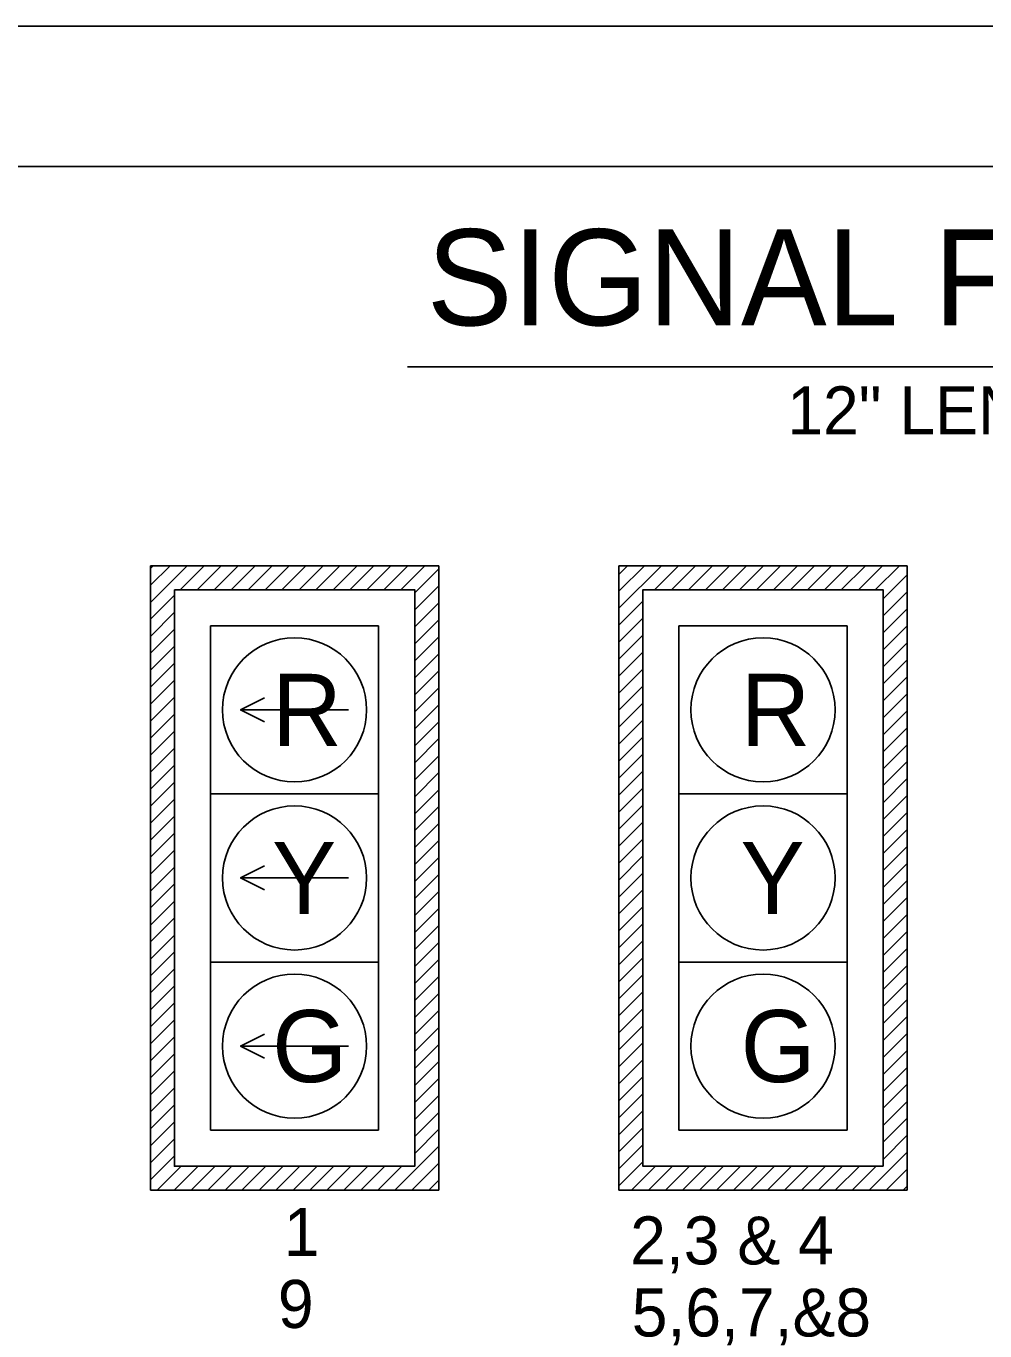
# Model space of a CAD drawing. Extents: x 660063 to 664816, y 641756 to 643817.
# Drawn here: x 661614.4 to 661694.2, y 642780 to 642888.7 of the extents above; entities that cross this region are included whole.
import ezdxf

# ---------------------------------------------------------------- set-up
doc = ezdxf.new("R2010")
doc.units = 0
for name, color, linetype in [('Default', 7, 'Continuous'), ('R_Border', 7, 'Continuous'), ('R_No Plot', 7, 'Continuous'), ('T_Drafting', 7, 'Continuous'), ('T_Notes', 7, 'Continuous')]:
    doc.layers.add(name, color=color, linetype=linetype)

msp = doc.modelspace()

# ---------------------------------------------------------------- linework, layer by layer
at = {"layer": 'R_Border'}
msp.add_line((661447.99, 642876.97), (662396.53, 642876.97), dxfattribs=at)
at = {"layer": 'R_No Plot'}
msp.add_line((661410.79, 642888.66), (662410.79, 642888.66), dxfattribs=at)
msp.add_lwpolyline([(661410.77, 642888.66), (662410.79, 642888.66), (662410.79, 642248.64), (661410.77, 642248.64)], close=True, dxfattribs=at)
at = {"layer": 'T_Drafting'}
for p, q in [((661624.76, 642843.72), (661648.76, 642843.72)), ((661624.76, 642791.72), (661624.76, 642843.72)), ((661624.76, 642840.67), (661627.81, 642843.72)), ((661624.76, 642842.09), (661626.4, 642843.72)), ((661624.76, 642843.5), (661624.99, 642843.72)), ((661627.23, 642841.72), (661629.23, 642843.72)), ((661628.64, 642841.72), (661630.64, 642843.72)), ((661630.06, 642841.72), (661632.06, 642843.72)), ((661631.47, 642841.72), (661633.47, 642843.72)), ((661632.89, 642841.72), (661634.89, 642843.72)), ((661634.3, 642841.72), (661636.3, 642843.72)), ((661635.71, 642841.72), (661637.71, 642843.72)), ((661637.13, 642841.72), (661639.13, 642843.72)), ((661638.54, 642841.72), (661640.54, 642843.72)), ((661639.96, 642841.72), (661641.96, 642843.72)), ((661641.37, 642841.72), (661643.37, 642843.72)), ((661642.78, 642841.72), (661644.78, 642843.72)), ((661644.2, 642841.72), (661646.2, 642843.72)), ((661645.61, 642841.72), (661647.61, 642843.72)), ((661646.76, 642841.46), (661648.76, 642843.46)), ((661648.76, 642843.72), (661648.76, 642791.72)), ((661687.76, 642843.72), (661663.76, 642843.72)), ((661663.76, 642843.72), (661663.76, 642791.72)), ((661663.76, 642840.18), (661667.31, 642843.72)), ((661663.76, 642841.59), (661665.9, 642843.72)), ((661663.76, 642843), (661664.48, 642843.72)), ((661666.73, 642841.72), (661668.73, 642843.72)), ((661668.14, 642841.72), (661670.14, 642843.72)), ((661669.55, 642841.72), (661671.55, 642843.72)), ((661670.97, 642841.72), (661672.97, 642843.72)), ((661672.38, 642841.72), (661674.38, 642843.72)), ((661673.8, 642841.72), (661675.8, 642843.72)), ((661675.21, 642841.72), (661677.21, 642843.72)), ((661676.62, 642841.72), (661678.62, 642843.72)), ((661678.04, 642841.72), (661680.04, 642843.72)), ((661679.45, 642841.72), (661681.45, 642843.72)), ((661680.87, 642841.72), (661682.87, 642843.72)), ((661682.28, 642841.72), (661684.28, 642843.72)), ((661683.7, 642841.72), (661685.7, 642843.72)), ((661685.11, 642841.72), (661687.11, 642843.72)), ((661687.76, 642791.72), (661687.76, 642843.72)), ((661685.76, 642840.96), (661687.76, 642842.96)), ((661624.76, 642839.26), (661626.76, 642841.26)), ((661646.76, 642840.04), (661648.76, 642842.04)), ((661685.76, 642839.55), (661687.76, 642841.55)), ((661646.76, 642838.63), (661648.76, 642840.63)), ((661663.76, 642838.76), (661665.76, 642840.76)), ((661685.76, 642838.13), (661687.76, 642840.13)), ((661624.76, 642837.84), (661626.76, 642839.84)), ((661646.76, 642837.22), (661648.76, 642839.22)), ((661663.76, 642837.35), (661665.76, 642839.35)), ((661624.76, 642836.43), (661626.76, 642838.43)), ((661629.76, 642838.72), (661643.76, 642838.72)), ((661629.76, 642838.72), (661629.76, 642824.72)), ((661643.76, 642838.72), (661643.76, 642824.72)), ((661663.76, 642835.93), (661665.76, 642837.93)), ((661668.76, 642838.72), (661682.76, 642838.72)), ((661668.76, 642838.72), (661668.76, 642824.72)), ((661682.76, 642838.72), (661682.76, 642824.72)), ((661685.76, 642836.72), (661687.76, 642838.72)), ((661624.76, 642835.02), (661626.76, 642837.02)), ((661646.76, 642835.8), (661648.76, 642837.8)), ((661685.76, 642835.31), (661687.76, 642837.31)), ((661646.76, 642834.39), (661648.76, 642836.39)), ((661663.76, 642834.52), (661665.76, 642836.52)), ((661685.76, 642833.89), (661687.76, 642835.89)), ((661624.76, 642833.6), (661626.76, 642835.6)), ((661646.76, 642832.97), (661648.76, 642834.97)), ((661663.76, 642833.1), (661665.76, 642835.1)), ((661624.76, 642832.19), (661626.76, 642834.19)), ((661646.76, 642831.56), (661648.76, 642833.56)), ((661663.76, 642831.69), (661665.76, 642833.69)), ((661685.76, 642832.48), (661687.76, 642834.48)), ((661624.76, 642830.77), (661626.76, 642832.77)), ((661685.76, 642831.06), (661687.76, 642833.06)), ((661624.76, 642829.36), (661626.76, 642831.36)), ((661641.26, 642831.72), (661632.26, 642831.72)), ((661646.76, 642830.15), (661648.76, 642832.15)), ((661663.76, 642830.28), (661665.76, 642832.28)), ((661685.76, 642829.65), (661687.76, 642831.65)), ((661646.76, 642828.73), (661648.76, 642830.73)), ((661663.76, 642828.86), (661665.76, 642830.86)), ((661685.76, 642828.23), (661687.76, 642830.23)), ((661624.76, 642827.94), (661626.76, 642829.94)), ((661646.76, 642827.32), (661648.76, 642829.32)), ((661663.76, 642827.45), (661665.76, 642829.45)), ((661624.76, 642826.53), (661626.76, 642828.53)), ((661663.76, 642826.03), (661665.76, 642828.03)), ((661685.76, 642826.82), (661687.76, 642828.82)), ((661624.76, 642825.12), (661626.76, 642827.12)), ((661646.76, 642825.9), (661648.76, 642827.9)), ((661685.76, 642825.41), (661687.76, 642827.41)), ((661646.76, 642824.49), (661648.76, 642826.49)), ((661663.76, 642824.62), (661665.76, 642826.62)), ((661685.76, 642823.99), (661687.76, 642825.99)), ((661624.76, 642823.7), (661626.76, 642825.7)), ((661646.76, 642823.07), (661648.76, 642825.07)), ((661663.76, 642823.2), (661665.76, 642825.2)), ((661624.76, 642822.29), (661626.76, 642824.29)), ((661629.76, 642824.72), (661643.76, 642824.72)), ((661629.76, 642824.72), (661629.76, 642810.72)), ((661643.76, 642824.72), (661643.76, 642810.72)), ((661663.76, 642821.79), (661665.76, 642823.79)), ((661668.76, 642824.72), (661682.76, 642824.72)), ((661668.76, 642824.72), (661668.76, 642810.72)), ((661682.76, 642824.72), (661682.76, 642810.72)), ((661685.76, 642822.58), (661687.76, 642824.58)), ((661624.76, 642820.87), (661626.76, 642822.87)), ((661646.76, 642821.66), (661648.76, 642823.66)), ((661685.76, 642821.16), (661687.76, 642823.16)), ((661646.76, 642820.25), (661648.76, 642822.25)), ((661663.76, 642820.38), (661665.76, 642822.38)), ((661685.76, 642819.75), (661687.76, 642821.75)), ((661624.76, 642819.46), (661626.76, 642821.46)), ((661646.76, 642818.83), (661648.76, 642820.83)), ((661663.76, 642818.96), (661665.76, 642820.96)), ((661624.76, 642818.04), (661626.76, 642820.04)), ((661646.76, 642817.42), (661648.76, 642819.42)), ((661663.76, 642817.55), (661665.76, 642819.55)), ((661685.76, 642818.33), (661687.76, 642820.33)), ((661624.76, 642816.63), (661626.76, 642818.63)), ((661685.76, 642816.92), (661687.76, 642818.92)), ((661624.76, 642815.22), (661626.76, 642817.22)), ((661641.26, 642817.72), (661632.26, 642817.72)), ((661646.76, 642816), (661648.76, 642818)), ((661663.76, 642816.13), (661665.76, 642818.13)), ((661685.76, 642815.51), (661687.76, 642817.51)), ((661646.76, 642814.59), (661648.76, 642816.59)), ((661663.76, 642814.72), (661665.76, 642816.72)), ((661685.76, 642814.09), (661687.76, 642816.09)), ((661624.76, 642813.8), (661626.76, 642815.8)), ((661646.76, 642813.17), (661648.76, 642815.17)), ((661663.76, 642813.31), (661665.76, 642815.31)), ((661624.76, 642812.39), (661626.76, 642814.39)), ((661685.76, 642812.68), (661687.76, 642814.68)), ((661624.76, 642810.97), (661626.76, 642812.97)), ((661646.76, 642811.76), (661648.76, 642813.76)), ((661663.76, 642811.89), (661665.76, 642813.89)), ((661685.76, 642811.26), (661687.76, 642813.26)), ((661646.76, 642810.35), (661648.76, 642812.35)), ((661663.76, 642810.48), (661665.76, 642812.48)), ((661685.76, 642809.85), (661687.76, 642811.85)), ((661624.76, 642809.56), (661626.76, 642811.56)), ((661629.76, 642810.72), (661643.76, 642810.72)), ((661629.76, 642810.72), (661629.76, 642796.72)), ((661643.76, 642810.72), (661643.76, 642796.72)), ((661646.76, 642808.93), (661648.76, 642810.93)), ((661663.76, 642809.06), (661665.76, 642811.06)), ((661668.76, 642810.72), (661682.76, 642810.72)), ((661668.76, 642810.72), (661668.76, 642796.72)), ((661682.76, 642810.72), (661682.76, 642796.72)), ((661624.76, 642808.15), (661626.76, 642810.15)), ((661663.76, 642807.65), (661665.76, 642809.65)), ((661685.76, 642808.43), (661687.76, 642810.43)), ((661624.76, 642806.73), (661626.76, 642808.73)), ((661646.76, 642807.52), (661648.76, 642809.52)), ((661685.76, 642807.02), (661687.76, 642809.02)), ((661646.76, 642806.1), (661648.76, 642808.1)), ((661663.76, 642806.23), (661665.76, 642808.23)), ((661685.76, 642805.61), (661687.76, 642807.61)), ((661624.76, 642805.32), (661626.76, 642807.32)), ((661646.76, 642804.69), (661648.76, 642806.69)), ((661663.76, 642804.82), (661665.76, 642806.82)), ((661624.76, 642803.9), (661626.76, 642805.9)), ((661646.76, 642803.27), (661648.76, 642805.27)), ((661663.76, 642803.41), (661665.76, 642805.41)), ((661685.76, 642804.19), (661687.76, 642806.19)), ((661624.76, 642802.49), (661626.76, 642804.49)), ((661685.76, 642802.78), (661687.76, 642804.78)), ((661624.76, 642801.07), (661626.76, 642803.07)), ((661641.26, 642803.72), (661632.26, 642803.72)), ((661646.76, 642801.86), (661648.76, 642803.86)), ((661663.76, 642801.99), (661665.76, 642803.99)), ((661685.76, 642801.36), (661687.76, 642803.36)), ((661646.76, 642800.45), (661648.76, 642802.45)), ((661663.76, 642800.58), (661665.76, 642802.58)), ((661685.76, 642799.95), (661687.76, 642801.95)), ((661624.76, 642799.66), (661626.76, 642801.66)), ((661646.76, 642799.03), (661648.76, 642801.03)), ((661663.76, 642799.16), (661665.76, 642801.16)), ((661624.76, 642798.25), (661626.76, 642800.25)), ((661685.76, 642798.54), (661687.76, 642800.54)), ((661624.76, 642796.83), (661626.76, 642798.83)), ((661646.76, 642797.62), (661648.76, 642799.62)), ((661663.76, 642797.75), (661665.76, 642799.75)), ((661685.76, 642797.12), (661687.76, 642799.12)), ((661646.76, 642796.2), (661648.76, 642798.2)), ((661663.76, 642796.33), (661665.76, 642798.33)), ((661685.76, 642795.71), (661687.76, 642797.71)), ((661624.76, 642795.42), (661626.76, 642797.42)), ((661629.76, 642796.72), (661643.76, 642796.72)), ((661646.76, 642794.79), (661648.76, 642796.79)), ((661663.76, 642794.92), (661665.76, 642796.92)), ((661668.76, 642796.72), (661682.76, 642796.72)), ((661624.76, 642794), (661626.76, 642796)), ((661663.76, 642793.51), (661665.76, 642795.51)), ((661685.76, 642794.29), (661687.76, 642796.29)), ((661624.76, 642792.59), (661626.76, 642794.59)), ((661645.11, 642791.72), (661648.76, 642795.38)), ((661684.61, 642791.72), (661687.76, 642794.88)), ((661625.31, 642791.72), (661627.31, 642793.72)), ((661626.73, 642791.72), (661628.73, 642793.72)), ((661628.14, 642791.72), (661630.14, 642793.72)), ((661629.55, 642791.72), (661631.55, 642793.72)), ((661630.97, 642791.72), (661632.97, 642793.72)), ((661632.38, 642791.72), (661634.38, 642793.72)), ((661633.8, 642791.72), (661635.8, 642793.72)), ((661635.21, 642791.72), (661637.21, 642793.72)), ((661636.63, 642791.72), (661638.63, 642793.72)), ((661638.04, 642791.72), (661640.04, 642793.72)), ((661639.45, 642791.72), (661641.45, 642793.72)), ((661640.87, 642791.72), (661642.87, 642793.72)), ((661642.28, 642791.72), (661644.28, 642793.72)), ((661643.7, 642791.72), (661645.7, 642793.72)), ((661646.53, 642791.72), (661648.76, 642793.96)), ((661663.76, 642792.09), (661665.76, 642794.09)), ((661664.81, 642791.72), (661666.81, 642793.72)), ((661666.22, 642791.72), (661668.22, 642793.72)), ((661667.64, 642791.72), (661669.64, 642793.72)), ((661669.05, 642791.72), (661671.05, 642793.72)), ((661670.47, 642791.72), (661672.47, 642793.72)), ((661671.88, 642791.72), (661673.88, 642793.72)), ((661673.29, 642791.72), (661675.29, 642793.72)), ((661674.71, 642791.72), (661676.71, 642793.72)), ((661676.12, 642791.72), (661678.12, 642793.72)), ((661677.54, 642791.72), (661679.54, 642793.72)), ((661678.95, 642791.72), (661680.95, 642793.72)), ((661680.37, 642791.72), (661682.37, 642793.72)), ((661681.78, 642791.72), (661683.78, 642793.72)), ((661683.19, 642791.72), (661685.19, 642793.72)), ((661686.02, 642791.72), (661687.76, 642793.46)), ((661647.94, 642791.72), (661648.76, 642792.55)), ((661648.76, 642791.72), (661624.76, 642791.72)), ((661663.76, 642791.72), (661687.76, 642791.72)), ((661687.44, 642791.72), (661687.76, 642792.05))]:
    msp.add_line(p, q, dxfattribs=at)
for points in [[(661626.76, 642841.72), (661646.76, 642841.72), (661646.76, 642793.72), (661626.76, 642793.72)], [(661685.76, 642793.72), (661685.76, 642841.72), (661665.76, 642841.72), (661665.76, 642793.72)]]:
    msp.add_lwpolyline(points, close=True, dxfattribs=at)
for points in [[(661634.26, 642832.72), (661632.26, 642831.72), (661634.26, 642830.72)], [(661634.26, 642818.72), (661632.26, 642817.72), (661634.26, 642816.72)], [(661634.26, 642804.72), (661632.26, 642803.72), (661634.26, 642802.72)]]:
    msp.add_lwpolyline(points, dxfattribs=at)
for centre in [(661636.76, 642831.72), (661675.76, 642831.72), (661636.76, 642817.72), (661675.76, 642817.72), (661636.76, 642803.72), (661675.76, 642803.72)]:
    msp.add_circle(centre, 6, dxfattribs=at)
at = {"layer": 'T_Notes'}
msp.add_line((661646.17, 642860.27), (661732.14, 642860.27), dxfattribs=at)

# ---------------------------------------------------------------- texts
at = {"layer": 'Default'}
for s, p in [('1', (661635.86, 642786.25)), ('9', (661635.37, 642780.25))]:
    msp.add_text(s, height=4, dxfattribs=at).set_placement(p)
at = {"layer": 'T_Drafting'}
msp.add_text('12" LENSES', height=4, rotation=0.072, dxfattribs=at).set_placement((661677.78, 642854.65))
for s, p in [('R', (661634.9, 642828.72)), ('R', (661673.9, 642828.72)), ('Y', (661634.88, 642814.72)), ('Y', (661673.88, 642814.72)), ('G', (661634.9, 642800.72)), ('G', (661673.9, 642800.72))]:
    msp.add_text(s, height=6, dxfattribs=at).set_placement(p)
at = {"layer": 'T_Notes'}
for s, height, p in [('SIGNAL FACES', 8, (661647.77, 642863.74)), ('2,3 & 4', 4, (661664.7, 642785.54)), ('5,6,7,&8', 4, (661664.83, 642779.54))]:
    msp.add_text(s, height=height, dxfattribs=at).set_placement(p)

doc.saveas('drawing.dxf')
